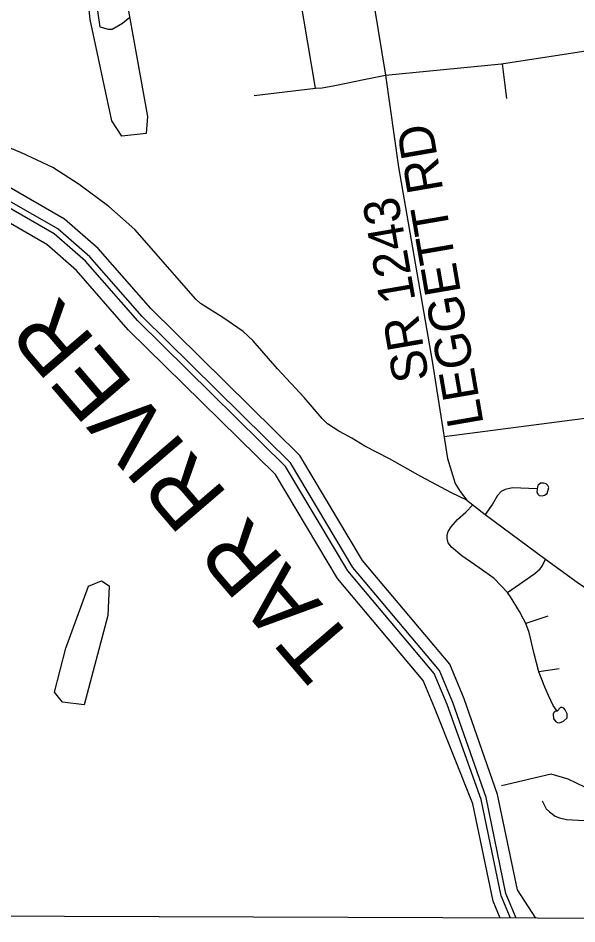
# Model space of a CAD drawing. Extents: x 2364794 to 2387902, y 795230 to 810426.
# Drawn here: x 2365657 to 2366052, y 800399 to 801040 of the extents above; entities that cross this region are included whole.
import ezdxf

# ---------------------------------------------------------------- set-up
doc = ezdxf.new("R2010")
doc.units = 0
for name, color, linetype in [('Default', 7, 'Continuous'), ('Plot Label CELL', 7, 'Continuous'), ('User Information Notes CELL', 7, 'Continuous')]:
    doc.layers.add(name, color=color, linetype=linetype)

msp = doc.modelspace()

# ---------------------------------------------------------------- linework, layer by layer
at = {"layer": 'Default'}
msp.add_lwpolyline([(2365221.07, 800406.27), (2365228.68, 802558.07), (2367168.28, 802551.22), (2367160.68, 800399.42)], close=True, dxfattribs=at)
msp.add_lwpolyline([(2365221.07, 800406.27), (2365228.68, 802558.07), (2367168.28, 802551.22), (2367160.68, 800399.42)], close=True, dxfattribs=at)
at = {"layer": 'Plot Label CELL'}
for p, q in [((2365866.87, 800990.38), (2365856.06, 801054.68)), ((2365916.44, 800999.66), (2365998.45, 801007.58)), ((2365823.61, 800985.13), (2365866.87, 800990.38)), ((2366071.26, 800758.51), (2365957.83, 800743.89)), ((2366031.19, 800616.96), (2366015.7, 800611.77)), ((2366039.31, 800579.67), (2366024.94, 800577.61))]:
    msp.add_line(p, q, dxfattribs=at)
for points in [[(2365883.31, 801194.17), (2365897.22, 801109.53), (2365908.58, 801046.96), (2365916.44, 800999.66), (2365925.73, 800934.59), (2365949.43, 800797.29), (2365960.28, 800728.51), (2365965.75, 800710.79), (2365969.29, 800705.11), (2365974.01, 800699.16), (2365986.96, 800688.84), (2366029.57, 800657.45), (2366052.09, 800641.03), (2366065.31, 800632.03)], [(2365747.24, 800958.36), (2365730.08, 800956.45), (2365722.86, 800967.31), (2365707.62, 801039.09), (2365702.46, 801090.93), (2365706.9, 801106.45), (2365718.09, 801104.78), (2365725.18, 801097.53), (2365748.23, 800970.27), (2365747.24, 800958.36)], [(2365711.96, 801051.54), (2365714.34, 801033.87), (2365720.23, 801032.22), (2365723.07, 801032.21), (2365730.4, 801036.45), (2365735.7, 801040.7)], [(2365998.45, 801007.58), (2366096.39, 801022.62), (2366099.23, 801022.19), (2366102.08, 801020.69), (2366102.99, 801018.07), (2366106.18, 801002.79), (2366107.06, 801000.39), (2366107.96, 800999.09), (2366109.72, 800997.8), (2366111.9, 800996.73), (2366114.75, 800996.53), (2366182.02, 801005.64)], [(2365998.45, 801007.58), (2365998.88, 801007.62), (2366001.98, 800983.17)], [(2365866.87, 800990.38), (2365871.7, 800990.75), (2365880.66, 800992.37), (2365902.42, 800996.84), (2365916.44, 800999.66)], [(2365883.37, 800747.84), (2365875.48, 800752.94), (2365871.73, 800756.83), (2365858.92, 800771.59), (2365840.16, 800791.99), (2365822.73, 800811.94), (2365815.88, 800818.23), (2365801.39, 800828.16), (2365785.54, 800838.07), (2365782.24, 800841.12), (2365739.21, 800890.39), (2365720.7, 800906.84), (2365699.79, 800922.41), (2365681.11, 800934.27), (2365659.16, 800944.59), (2365634.38, 800954.86)], [(2365974.01, 800699.16), (2365963.11, 800704.27), (2365941.37, 800715.88), (2365919.19, 800728.38), (2365901.84, 800737.19), (2365892.61, 800742.79), (2365883.82, 800747.54), (2365883.37, 800747.84)], [(2366023.65, 800707.18), (2366023.46, 800704.77), (2366024.32, 800703.03), (2366025.23, 800702.39), (2366027.18, 800702.17), (2366028.94, 800702.64), (2366030.89, 800703.73), (2366031.95, 800707.91), (2366031.28, 800709.44), (2366030.17, 800710.73), (2366028.2, 800711.16), (2366026.01, 800711.14), (2366024.07, 800709.37), (2366023.65, 800707.18)], [(2366023.65, 800707.18), (2366006.35, 800707.88), (2366001.2, 800706.71), (2365998.29, 800705.27), (2365995.65, 800702.38), (2365992.07, 800696.33), (2365986.96, 800688.84)], [(2366002.72, 800633.83), (2365993.33, 800643.74), (2365982.81, 800651.29), (2365970.45, 800659.77), (2365963.09, 800665.73), (2365960.86, 800668.9), (2365960.14, 800672.06), (2365960.15, 800674.57), (2365960.69, 800676.81), (2365962.87, 800680.22), (2365967.37, 800685.48), (2365973.19, 800690.47), (2365978.26, 800695.87)], [(2366002.72, 800633.83), (2366021.96, 800647.26), (2366025.87, 800650.58), (2366027.18, 800652.45), (2366029.57, 800657.45)], [(2366015.7, 800611.77), (2366014.16, 800614.84), (2366011.27, 800620.29), (2366004.84, 800630.72), (2366002.72, 800633.83)], [(2366024.94, 800577.61), (2366021.69, 800590.41), (2366017.94, 800605.46), (2366015.7, 800611.77)], [(2366037.89, 800549.9), (2366035.01, 800553.82), (2366031.81, 800560.98), (2366029.12, 800566.79), (2366024.94, 800577.61)], [(2366037.89, 800549.9), (2366036.3, 800549.6), (2366035.47, 800549), (2366035.06, 800547.7), (2366035.36, 800544.4), (2366036.75, 800542.75), (2366038.03, 800541.9), (2366039.49, 800541.6), (2366042.31, 800542.72), (2366044.86, 800545.1), (2366044.94, 800547.86), (2366043.58, 800550.74), (2366042.68, 800551.91), (2366041.44, 800552.37), (2366040.27, 800552.33), (2366037.89, 800549.9)], [(2366057.34, 800496.19), (2366045.61, 800501.83), (2366033.65, 800505.37), (2365998.47, 800497.14)], [(2366027.27, 800486.41), (2366030.17, 800480.75), (2366032.37, 800478.58), (2366036.54, 800475.55), (2366039.61, 800474.49), (2366044.42, 800473.23), (2366083.03, 800471.04), (2366083.75, 800471.03)]]:
    msp.add_lwpolyline(points, dxfattribs=at)
at = {"layer": 'User Information Notes CELL'}
for points in [[(2365995.75, 800490.81), (2365972.09, 800558.53), (2365961.84, 800583.05), (2365900.25, 800656.33), (2365855.86, 800730.63), (2365750.42, 800834.56), (2365713.31, 800877), (2365689.57, 800897.76), (2365647.4, 800921.96), (2365600.93, 800936.12), (2365512.65, 800936.32), (2365494.24, 800938.9)], [(2365984.07, 800487.44), (2365960.06, 800554.6), (2365950.94, 800576.41), (2365889.94, 800648.98), (2365845.85, 800722.78), (2365741.23, 800825.9), (2365704.37, 800868.06), (2365682.2, 800887.44), (2365642.35, 800910.31), (2365599.04, 800923.51), (2365511.75, 800923.71), (2365482.63, 800927.78)], [(2365987.54, 800488.73), (2365964.14, 800555.93), (2365954.64, 800578.66), (2365893.44, 800651.47), (2365849.25, 800725.44), (2365744.35, 800828.83), (2365707.4, 800871.09), (2365684.7, 800890.93), (2365644.06, 800914.26), (2365599.68, 800927.78), (2365512.06, 800927.98), (2365492.11, 800930.77)], [(2365978.2, 800484.41), (2365951.35, 800551.75), (2365943.06, 800571.6), (2365882.48, 800643.67), (2365838.61, 800717.1), (2365734.58, 800819.63), (2365697.9, 800861.58), (2365676.87, 800879.97), (2365638.7, 800901.88), (2365597.67, 800914.38), (2365511.11, 800914.58), (2365480.3, 800918.89)], [(2365720.12, 800617.47), (2365703.45, 800554.44), (2365687.95, 800556.15), (2365682.3, 800563.39), (2365690.48, 800594.42), (2365706.42, 800638.31), (2365715.62, 800642), (2365721.13, 800638.37), (2365720.12, 800617.47)], [(2366022.71, 800403.44), (2366009.75, 800423.52), (2365995.75, 800490.81)], [(2365997.54, 800403.53), (2365992.54, 800415.4), (2365978.2, 800484.41)], [(2366004.89, 800403.5), (2365998.23, 800419.32), (2365984.07, 800487.44)], [(2366008.97, 800403.49), (2366001.65, 800420.9), (2365987.54, 800488.73)]]:
    msp.add_lwpolyline(points, dxfattribs=at)

# ---------------------------------------------------------------- texts
at = {"layer": 'Default'}
for s, height, rotation, p in [('LEGGETT RD', 25.362, 99.79445, (2365985.93, 800753.09)), ('SR 1243 ', 25.362, 99.79445, (2365947.41, 800784.76)), ('TAR RIVER', 45.927, 130.66871, (2365897.11, 800596.71))]:
    msp.add_text(s, height=height, rotation=rotation, dxfattribs=at).set_placement(p)

doc.saveas('drawing.dxf')
